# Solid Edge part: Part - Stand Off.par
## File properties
Author: hhakima
Template: Normal.par
Last saved by: hhakima
Revision: 5
Application: Solid Edge
Material: Aluminum, 6061-T6
Face Style: Aluminum
Fill Style: ANSI38(Aluminum)
Virtual Style: Polished aluminum
Coef. of Thermal Exp: 2.3e-05
Thermal Conductivity: 180.0
Specific Heat: 920.0
Modulus of Elasticity: 68947570000.0
Poission's Ratio: 0.33
Yield Stress: 275790280.0
Ultimate Stress: 310264065.0
Elongation: 0.0
Density: 2712.000 kg/m^3
Accuracy: 0.990
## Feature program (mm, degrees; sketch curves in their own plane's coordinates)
sketch for "unnamed Protrusion 1" plane through (0, 0, 0) normal (0, 0, 1) x-axis (1, 0, 0)
  circle centre (-32.2752, 20.2968) radius 2
extrude "unnamed Protrusion 1" add finite 3 along -normal
sketch for "Hole_1" plane through (-32.2752, 20.2968, 0) normal (0, 0, 1) x-axis (1, 0, 0)
  hole centre (0, 0) bore radius 0.9
hole "Hole_1" diameter 1.8 through
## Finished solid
Body 1: solid body, 4 faces, 4 edges, 0 vertices.
  Faces by surface: cylinder 2, plane 2
  Edges by curve: circle 4
Bounding box of the edges (mm): 4.000 x 4.000 x 3.000, from (-34.2752, 18.2968, -3) to (-30.2752, 22.2968, 0).
Cylindrical faces by radius (mm): R0.9 x1, R2 x1
Planar faces by outward normal: +z 1, -z 1
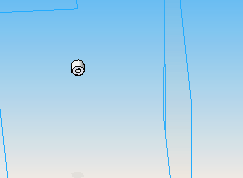
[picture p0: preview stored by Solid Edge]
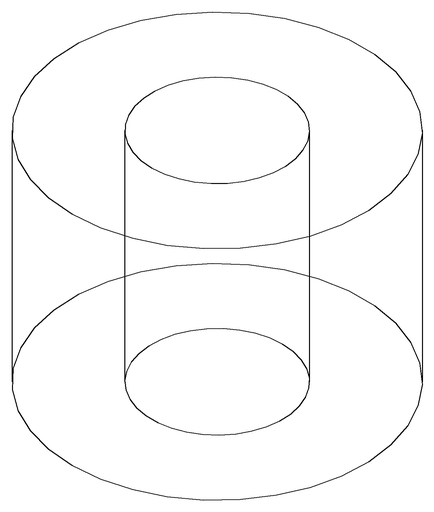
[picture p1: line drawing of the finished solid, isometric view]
